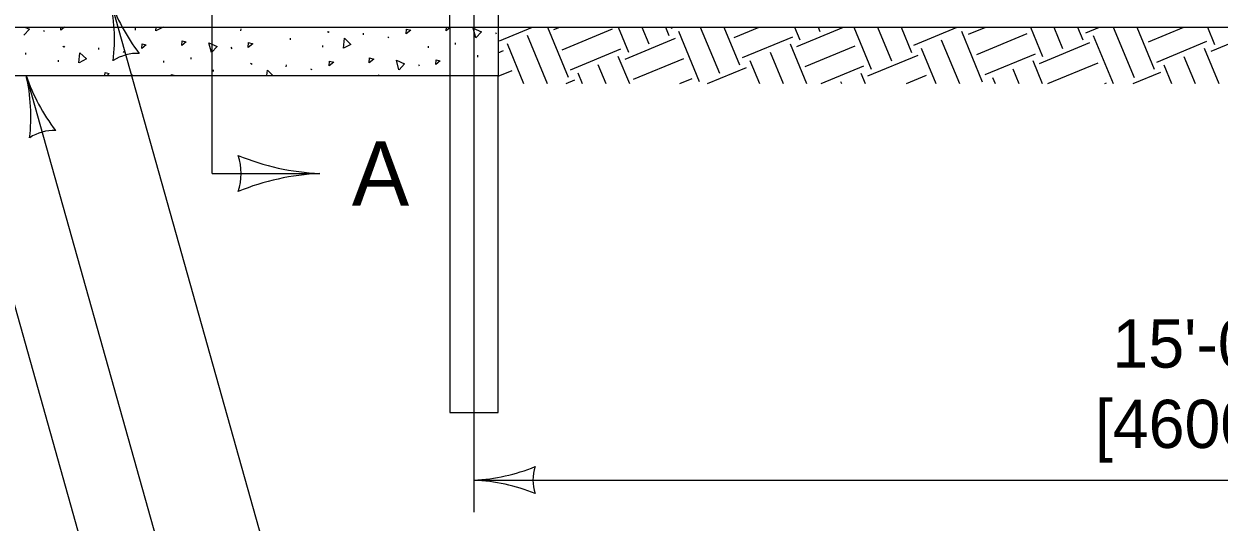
# Model space of a CAD drawing. Extents: x 49991.4 to 50021, y 49987.6 to 50011.4.
# Drawn here: x 50002.451 to 50003.939, y 49989.252 to 49989.872 of the extents above; entities that cross this region are included whole.
import ezdxf

# ---------------------------------------------------------------- set-up
doc = ezdxf.new("R2010")
doc.units = 0
for name, color, linetype in [('Level 1', 7, 'Continuous'), ('Level 2', 7, 'Continuous'), ('Level 3', 7, 'Continuous'), ('Level 4', 7, 'Continuous'), ('Level 5', 7, 'Continuous'), ('Level 6', 7, 'Continuous')]:
    doc.layers.add(name, color=color, linetype=linetype)

msp = doc.modelspace()

# ---------------------------------------------------------------- linework, layer by layer
at = {"layer": 'Level 1'}
for p, q in [((50003.0415, 49990.8281), (50003.0415, 49989.8078)), ((50002.9815, 49989.8678), (50002.9815, 49990.1665)), ((50000.4081, 49989.8678), (50004.9435, 49989.8678)), ((50002.3588, 49989.8678), (50003.0415, 49989.8678)), ((50002.4755, 49989.8642), (50002.4764, 49989.8625)), ((50002.5899, 49989.8642), (50002.59, 49989.8664)), ((50002.7213, 49989.8634), (50002.7214, 49989.8655)), ((50002.7551, 49989.8677), (50002.7551, 49989.8678)), ((50002.7829, 49989.8521), (50002.783, 49989.8542)), ((50002.829, 49989.8625), (50002.8303, 49989.8616)), ((50002.83, 49989.8624), (50002.8313, 49989.8615)), ((50002.8737, 49989.8582), (50002.8737, 49989.8604)), ((50002.904, 49989.8558), (50002.9053, 49989.8549)), ((50003.0382, 49989.861), (50003.0391, 49989.8593)), ((50003.0415, 49989.8678), (50004.9435, 49989.8678)), ((50003.0434, 49989.8509), (50003.0842, 49989.8678)), ((50003.0778, 49989.8578), (50003.1027, 49989.7976)), ((50003.103, 49989.8678), (50003.1288, 49989.8055)), ((50003.111, 49989.8647), (50003.1183, 49989.8678)), ((50003.1214, 49989.8397), (50003.184, 49989.8656)), ((50003.191, 49989.8678), (50003.2039, 49989.8367)), ((50003.2204, 49989.8678), (50003.229, 49989.847)), ((50003.2497, 49989.8678), (50003.254, 49989.8574)), ((50003.257, 49989.8665), (50003.26, 49989.8678)), ((50003.2659, 49989.8629), (50003.2918, 49989.8002)), ((50003.2932, 49989.8678), (50003.3169, 49989.8106)), ((50003.3225, 49989.8678), (50003.3419, 49989.821)), ((50003.3352, 49989.8549), (50003.3663, 49989.8678)), ((50003.3456, 49989.8298), (50003.4082, 49989.8558)), ((50003.4106, 49989.8678), (50003.4171, 49989.8521)), ((50003.4132, 49989.8437), (50003.4714, 49989.8678)), ((50003.4399, 49989.8678), (50003.4421, 49989.8625)), ((50003.4845, 49989.8678), (50003.5061, 49989.8156)), ((50003.5138, 49989.8678), (50003.5312, 49989.826)), ((50003.5432, 49989.8678), (50003.5562, 49989.8364)), ((50003.5592, 49989.8455), (50003.6131, 49989.8678)), ((50003.6182, 49989.8626), (50003.6441, 49989.7999)), ((50003.627, 49989.8589), (50003.6485, 49989.8678)), ((50003.6312, 49989.8678), (50003.6315, 49989.8672)), ((50003.6374, 49989.8338), (50003.7, 49989.8598)), ((50003.7041, 49989.8678), (50003.7193, 49989.8311)), ((50003.7334, 49989.8678), (50003.7443, 49989.8414)), ((50003.7628, 49989.8678), (50003.7694, 49989.8518)), ((50003.773, 49989.8607), (50003.7902, 49989.8678)), ((50003.7824, 49989.8572), (50003.807, 49989.7976)), ((50003.8073, 49989.8678), (50003.8333, 49989.8049)), ((50003.8367, 49989.8678), (50003.8584, 49989.8153)), ((50003.851, 49989.8495), (50003.8952, 49989.8678)), ((50003.9247, 49989.8678), (50003.9335, 49989.8464)), ((50003.9292, 49989.8378), (50003.9919, 49989.8638)), ((50002.4997, 49989.8443), (50002.501, 49989.8434)), ((50002.5007, 49989.8441), (50002.502, 49989.8433)), ((50002.5444, 49989.84), (50002.5445, 49989.8421)), ((50002.7089, 49989.8427), (50002.7099, 49989.841)), ((50002.8233, 49989.8428), (50002.8234, 49989.8449)), ((50002.9547, 49989.8419), (50002.9548, 49989.844)), ((50002.9886, 49989.8463), (50002.9886, 49989.8484)), ((50003.0527, 49989.8474), (50003.0733, 49989.7976)), ((50003.1318, 49989.8146), (50003.1944, 49989.8406)), ((50003.1996, 49989.8281), (50003.2622, 49989.854)), ((50003.405, 49989.8471), (50003.4255, 49989.7976)), ((50003.4236, 49989.8186), (50003.4862, 49989.8446)), ((50003.5681, 49989.8418), (50003.5864, 49989.7976)), ((50003.5931, 49989.8522), (50003.6157, 49989.7976)), ((50003.7154, 49989.8226), (50003.778, 49989.8486)), ((50003.8614, 49989.8244), (50003.924, 49989.8504)), ((50003.9204, 49989.8415), (50003.9386, 49989.7976)), ((50002.4537, 49989.8338), (50002.4537, 49989.836)), ((50002.4941, 49989.8245), (50002.4941, 49989.8267)), ((50002.5747, 49989.8376), (50002.576, 49989.8367)), ((50002.6255, 49989.8237), (50002.6255, 49989.8258)), ((50002.6593, 49989.828), (50002.6593, 49989.8302)), ((50003.0164, 49989.8306), (50003.0164, 49989.8328)), ((50003.0415, 49989.8359), (50003.0484, 49989.8388)), ((50003.1907, 49989.8317), (50003.2049, 49989.7976)), ((50003.21, 49989.803), (50003.2726, 49989.8289)), ((50003.3549, 49989.8264), (50003.3668, 49989.7976)), ((50003.38, 49989.8367), (50003.3962, 49989.7976)), ((50003.5018, 49989.807), (50003.5644, 49989.8329)), ((50003.6478, 49989.8088), (50003.7104, 49989.8347)), ((50003.7072, 49989.8261), (50003.719, 49989.7976)), ((50003.8953, 49989.8311), (50003.9092, 49989.7976)), ((50002.6871, 49989.8124), (50002.6872, 49989.8145)), ((50002.7332, 49989.8228), (50002.7345, 49989.8219)), ((50002.7342, 49989.8227), (50002.7355, 49989.8218)), ((50002.7778, 49989.8185), (50002.7779, 49989.8207)), ((50002.8081, 49989.8161), (50002.8094, 49989.8152)), ((50002.9424, 49989.8213), (50002.9433, 49989.8196)), ((50003.0415, 49989.8066), (50003.0588, 49989.8138)), ((50003.1406, 49989.811), (50003.1462, 49989.7976)), ((50003.1657, 49989.8213), (50003.1755, 49989.7976)), ((50003.302, 49989.7976), (50003.3506, 49989.8177)), ((50003.4437, 49989.7976), (50003.4966, 49989.8195)), ((50003.4929, 49989.8107), (50003.4983, 49989.7976)), ((50003.6822, 49989.8157), (50003.6896, 49989.7976)), ((50003.7258, 49989.7976), (50003.7884, 49989.8235)), ((50003.8321, 49989.7976), (50003.8666, 49989.8119)), ((50003.8703, 49989.8208), (50003.8799, 49989.7976)), ((50002.3588, 49989.8078), (50003.0415, 49989.8078)), ((50002.8927, 49989.8078), (50002.8928, 49989.8087)), ((50003.1261, 49989.7976), (50003.137, 49989.8021)), ((50003.2678, 49989.7976), (50003.283, 49989.8039)), ((50003.4679, 49989.8003), (50003.469, 49989.7976)), ((50003.55, 49989.7976), (50003.5748, 49989.8079)), ((50003.6571, 49989.8053), (50003.6603, 49989.7976)), ((50003.7967, 49989.7976), (50003.7988, 49989.7985))]:
    msp.add_line(p, q, dxfattribs=at)
for points in [[(50002.4521, 49989.8678), (50002.4581, 49989.8652), (50002.4512, 49989.8577)], [(50002.497, 49989.864), (50002.4972, 49989.8678)], [(50002.5015, 49989.8678), (50002.497, 49989.864)], [(50002.6155, 49989.8631), (50002.6159, 49989.8678)], [(50002.6245, 49989.8678), (50002.6155, 49989.8631)], [(50002.8489, 49989.8417), (50002.8501, 49989.8541), (50002.8582, 49989.8464), (50002.8491, 49989.8417)], [(50002.9271, 49989.8593), (50002.9275, 49989.8653), (50002.9327, 49989.8639), (50002.9271, 49989.8593)], [(50002.9769, 49989.8632), (50002.9772, 49989.8678)], [(50002.9824, 49989.8678), (50002.9769, 49989.8632)], [(50003.0137, 49989.8543), (50003.0106, 49989.8664), (50003.0208, 49989.862), (50003.0139, 49989.8544)], [(50002.5979, 49989.8411), (50002.5982, 49989.847), (50002.6034, 49989.8457), (50002.5979, 49989.8411)], [(50002.6477, 49989.8449), (50002.648, 49989.8509), (50002.6532, 49989.8496), (50002.6477, 49989.8449)], [(50002.6845, 49989.8361), (50002.6813, 49989.8482), (50002.6916, 49989.8437), (50002.6846, 49989.8362)], [(50002.7304, 49989.8425), (50002.7307, 49989.8485), (50002.736, 49989.8472), (50002.7304, 49989.8425)], [(50002.5196, 49989.8234), (50002.5208, 49989.8359), (50002.5289, 49989.8282), (50002.5198, 49989.8235)], [(50002.8313, 49989.8196), (50002.8316, 49989.8256), (50002.8369, 49989.8243), (50002.8313, 49989.8196)], [(50002.8811, 49989.8235), (50002.8814, 49989.8295), (50002.8867, 49989.8281), (50002.8811, 49989.8235)], [(50002.9179, 49989.8146), (50002.9148, 49989.8267), (50002.925, 49989.8223), (50002.9181, 49989.8148)], [(50002.9638, 49989.8211), (50002.9642, 49989.8271), (50002.9694, 49989.8257), (50002.9638, 49989.8211)], [(50002.552, 49989.8078), (50002.5521, 49989.8112), (50002.5574, 49989.8099), (50002.5549, 49989.8078)], [(50002.7536, 49989.8078), (50002.7542, 49989.8144), (50002.7612, 49989.8078)], [(50002.5857, 49989.8078), (50002.5855, 49989.8085), (50002.5871, 49989.8078)], [(50002.6348, 49989.8078), (50002.6349, 49989.8088), (50002.6389, 49989.8078)]]:
    msp.add_lwpolyline(points, dxfattribs=at)
at = {"layer": 'Level 3'}
for p, q in [((50002.558, 49989.9038), (50002.765, 49989.1673)), ((50002.3588, 49989.8078), (50002.6232, 49988.8673)), ((50002.4539, 49989.8078), (50002.676, 49989.0173)), ((50003.0115, 49989.3038), (50004.8516, 49989.3038))]:
    msp.add_line(p, q, dxfattribs=at)
for centre, radius, start, end in [((50002.3416, 49989.8525), 0.2223, 353.155, 13.3385), ((50002.7789, 49989.9779), 0.233, 198.5263, 217.7761), ((50002.5927, 49989.7804), 0.0548, 87.8378, 123.5602), ((50002.2375, 49989.7565), 0.2223, 353.155, 13.3385), ((50002.6748, 49989.8818), 0.233, 198.5263, 217.7761), ((50002.4886, 49989.6844), 0.0548, 87.8378, 123.5602), ((50002.8316, 49989.9818), 0.2964, 247.456, 267.6395), ((50002.6485, 49989.6856), 0.073, 342.1388, 17.8612), ((50002.8347, 49989.3753), 0.3107, 92.8273, 112.0772), ((50003, 49989.5365), 0.233, 272.8273, 292.0772), ((50003.1397, 49989.3038), 0.0548, 162.1388, 197.8612), ((50003.0023, 49989.0816), 0.2223, 67.456, 87.6395)]:
    msp.add_arc(centre, radius, start, end, dxfattribs=at)
at = {"layer": 'Level 4'}
for p, q in [((50002.9815, 49989.8678), (50002.9815, 49989.388)), ((50003.0415, 49989.388), (50003.0415, 49989.8078)), ((50002.9815, 49989.388), (50003.0415, 49989.388))]:
    msp.add_line(p, q, dxfattribs=at)
at = {"layer": 'Level 5'}
msp.add_line((50003.0115, 49989.2638), (50003.0115, 49990.9281), dxfattribs=at)
at = {"layer": 'Level 6'}
for q in [(50002.6855, 49990.0826), (50002.8194, 49989.6856)]:
    msp.add_line((50002.6855, 49989.6856), q, dxfattribs=at)

# ---------------------------------------------------------------- texts
at = {"layer": 'Level 2'}
for s, height, p in [('A', 0.08, (50002.8594, 49989.6456)), ('15\'-0"', 0.06, (50003.8063, 49989.4438)), ('[4600]', 0.06, (50003.7845, 49989.3438))]:
    msp.add_text(s, height=height, dxfattribs=at).set_placement(p)

doc.saveas('drawing.dxf')
